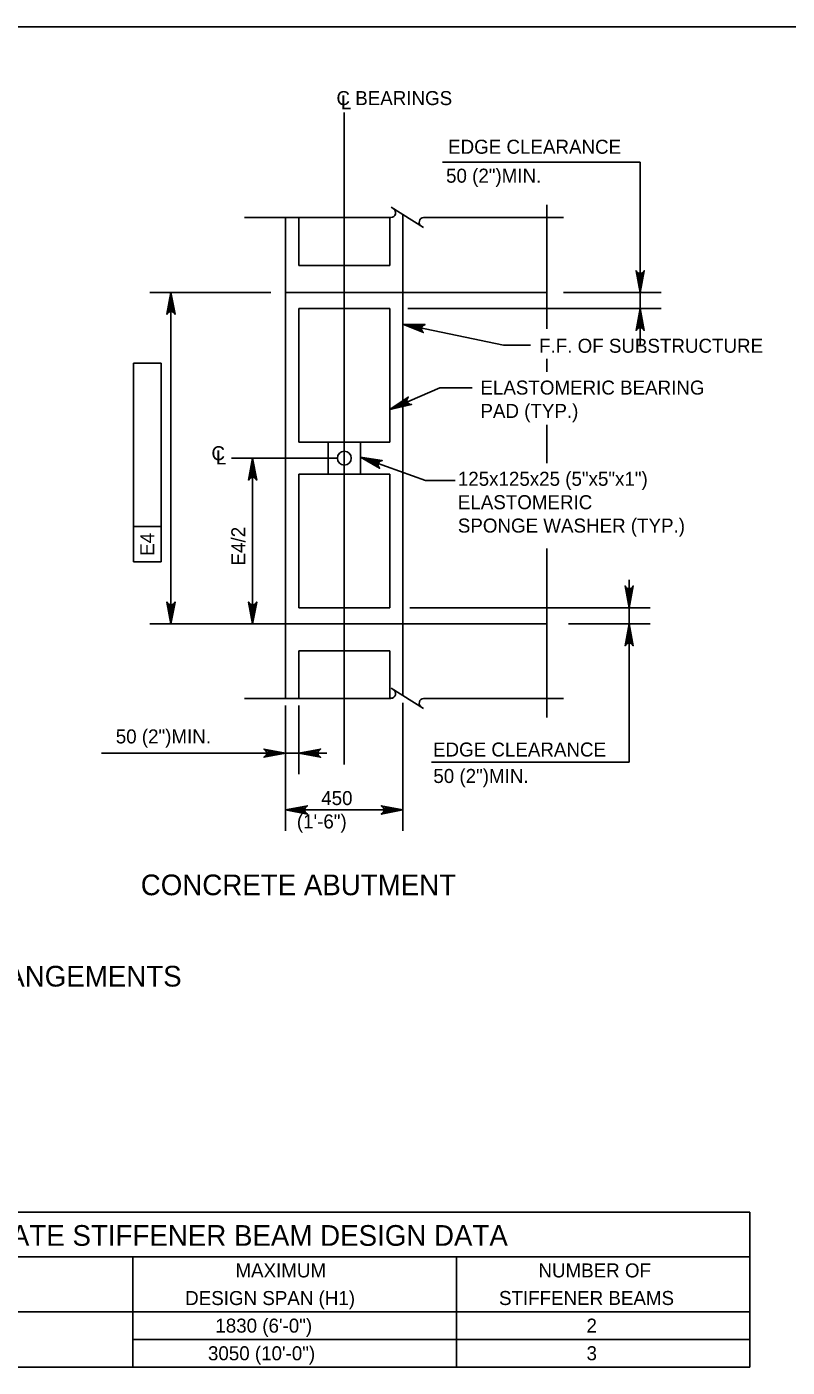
# Model space of a CAD drawing. Extents: x 638268 to 640277, y 295465 to 298435.
# Drawn here: x 639926.8 to 640089.4, y 297539.8 to 297826.5 of the extents above; entities that cross this region are included whole.
import ezdxf

# ---------------------------------------------------------------- set-up
doc = ezdxf.new("R2010")
doc.units = 0
for name, color, linetype in [('2', 7, 'Continuous'), ('3', 7, 'Continuous'), ('4', 7, 'Continuous'), ('8', 7, 'Continuous')]:
    doc.layers.add(name, color=color, linetype=linetype)

msp = doc.modelspace()

# ---------------------------------------------------------------- linework, layer by layer
at = {"layer": '2'}
msp.add_line((639316.46, 297826.46), (640102.46, 297826.46), dxfattribs=at)
at = {"layer": '3'}
for p, q in [((640004.71, 297787.87), (640011.64, 297783.51)), ((640038.02, 297788.37), (640038.02, 297761.88)), ((639973.35, 297785.69), (640004.63, 297785.69)), ((639982.12, 297682.85), (639982.12, 297785.69)), ((640007.22, 297786.29), (640007.22, 297683.45)), ((640011.63, 297785.69), (640041.52, 297785.69)), ((639984.93, 297775.38), (640004.41, 297775.38)), ((639978.92, 297769.64), (639953.09, 297769.64)), ((639957.59, 297698.77), (639957.59, 297769.64)), ((639982.12, 297769.64), (640038.02, 297769.64)), ((639984.93, 297766.19), (640004.41, 297766.19)), ((640038.02, 297755.46), (640038.02, 297752.64)), ((640038.02, 297741.36), (640038.02, 297733.14)), ((639984.93, 297737.65), (640004.41, 297737.65)), ((639984.93, 297730.76), (640004.41, 297730.76)), ((640038.02, 297714.9), (640038.02, 297678.78)), ((639984.93, 297702.22), (640004.41, 297702.22)), ((639979.62, 297698.77), (639953.09, 297698.77)), ((639982.12, 297698.77), (640038.02, 297698.77)), ((639984.93, 297693.03), (640004.41, 297693.03)), ((640004.71, 297685.03), (640011.64, 297680.68)), ((639973.35, 297682.85), (640004.63, 297682.85)), ((640011.63, 297682.85), (640041.52, 297682.85))]:
    msp.add_line(p, q, dxfattribs=at)
for points in [[(639957.09, 297766.64), (639958.09, 297766.64), (639957.59, 297769.64)], [(639957.09, 297701.77), (639958.09, 297701.77), (639957.59, 297698.77)]]:
    msp.add_lwpolyline(points, close=True, dxfattribs=at)
for centre, start, end in [((640004.63, 297786.71), 270, 60), ((640011.72, 297784.67), 95.3286, 237.8672), ((640004.63, 297683.88), 270, 60), ((640011.72, 297681.83), 95.3286, 237.8672)]:
    msp.add_arc(centre, 1.02, start, end, dxfattribs=at)
at = {"layer": '4'}
for p, q in [((639994.67, 297668.74), (639994.67, 297808.16)), ((640015.69, 297797.49), (640057.96, 297797.49)), ((640057.96, 297769.64), (640057.96, 297797.49)), ((640041.52, 297769.64), (640062.46, 297769.64)), ((640057.96, 297766.19), (640057.96, 297769.64)), ((640008.28, 297766.19), (640062.46, 297766.19)), ((640057.96, 297766.19), (640057.96, 297758.34)), ((640028.73, 297758.36), (640034.52, 297758.36)), ((639949.56, 297712.01), (639949.56, 297754.53)), ((639949.56, 297754.53), (639955.46, 297754.53)), ((639955.46, 297712.01), (639955.46, 297754.53)), ((640015.13, 297749.27), (640021.98, 297749.27)), ((639993.11, 297734.2), (639970.56, 297734.2)), ((639975.06, 297698.77), (639975.06, 297734.2)), ((640012.02, 297729.44), (640018.39, 297729.44)), ((639949.56, 297719.57), (639955.46, 297719.57)), ((639949.56, 297712.01), (639955.46, 297712.01)), ((640055.59, 297705.22), (640055.59, 297708.22)), ((640008.71, 297702.22), (640060.09, 297702.22)), ((640055.59, 297702.22), (640055.59, 297698.77)), ((639993.11, 297698.77), (639970.56, 297698.77)), ((640042.65, 297698.77), (640060.09, 297698.77)), ((640055.59, 297695.77), (640055.59, 297669.24)), ((640007.22, 297681.89), (640007.22, 297654.5)), ((639982.12, 297681.29), (639982.12, 297666.62)), ((639982.12, 297681.29), (639982.12, 297654.5)), ((639984.93, 297681.29), (639984.93, 297666.62)), ((639979.12, 297671.12), (639942.72, 297671.12)), ((639984.93, 297671.12), (639982.12, 297671.12)), ((639987.93, 297671.12), (639990.93, 297671.12)), ((640013.33, 297669.24), (640055.59, 297669.24)), ((640007.22, 297659), (639982.12, 297659))]:
    msp.add_line(p, q, dxfattribs=at)
for points in [[(640057.96, 297769.64), (640057.08, 297774.3), (640057.33, 297773.94), (640057.64, 297773.75), (640057.96, 297773.7), (640058.27, 297773.75), (640058.58, 297773.94), (640058.83, 297774.3), (640057.96, 297769.64), (640058.58, 297773.94), (640058.27, 297773.75), (640057.96, 297769.64), (640057.96, 297773.7), (640057.64, 297773.75), (640057.96, 297769.64), (640057.33, 297773.94)], [(639957.59, 297769.64), (639958.47, 297764.98), (639958.22, 297765.34), (639957.91, 297765.52), (639957.59, 297765.57), (639957.28, 297765.52), (639956.97, 297765.34), (639956.72, 297764.98), (639957.59, 297769.64), (639956.97, 297765.34), (639957.28, 297765.52), (639957.59, 297769.64), (639957.59, 297765.57), (639957.91, 297765.52), (639957.59, 297769.64), (639958.22, 297765.34)], [(640057.96, 297766.19), (640058.83, 297761.53), (640058.58, 297761.89), (640058.27, 297762.08), (640057.96, 297762.13), (640057.64, 297762.08), (640057.33, 297761.89), (640057.08, 297761.53), (640057.96, 297766.19), (640057.33, 297761.89), (640057.64, 297762.08), (640057.96, 297766.19), (640057.96, 297762.13), (640058.27, 297762.08), (640057.96, 297766.19), (640058.58, 297761.89)], [(640007.22, 297762.89), (640028.73, 297758.36)], [(640007.22, 297762.89), (640011.96, 297762.78), (640011.56, 297762.61), (640011.31, 297762.35), (640011.19, 297762.05), (640011.18, 297761.74), (640011.3, 297761.39), (640011.6, 297761.07), (640007.22, 297762.89), (640011.3, 297761.39), (640011.18, 297761.74), (640007.22, 297762.89), (640011.19, 297762.05), (640011.31, 297762.35), (640007.22, 297762.89), (640011.56, 297762.61)], [(640004.41, 297744.64), (640015.13, 297749.26)], [(640004.41, 297744.64), (640008.35, 297747.29), (640008.12, 297746.92), (640008.07, 297746.56), (640008.14, 297746.25), (640008.32, 297745.99), (640008.61, 297745.77), (640009.04, 297745.69), (640004.41, 297744.64), (640008.61, 297745.77), (640008.32, 297745.99), (640004.41, 297744.64), (640008.14, 297746.25), (640008.07, 297746.56), (640004.41, 297744.64), (640008.12, 297746.92)], [(639975.06, 297734.2), (639975.94, 297729.54), (639975.69, 297729.9), (639975.38, 297730.09), (639975.06, 297730.14), (639974.75, 297730.09), (639974.44, 297729.9), (639974.19, 297729.54), (639975.06, 297734.2), (639974.44, 297729.9), (639974.75, 297730.09), (639975.06, 297734.2), (639975.06, 297730.14), (639975.38, 297730.09), (639975.06, 297734.2), (639975.69, 297729.9)], [(639998.11, 297734.44), (640012.02, 297729.44)], [(639998.11, 297734.44), (640002.79, 297733.69), (640002.37, 297733.57), (640002.09, 297733.34), (640001.94, 297733.07), (640001.88, 297732.75), (640001.95, 297732.4), (640002.2, 297732.04), (639998.11, 297734.44), (640001.95, 297732.4), (640001.88, 297732.75), (639998.11, 297734.44), (640001.94, 297733.07), (640002.09, 297733.34), (639998.11, 297734.44), (640002.37, 297733.57)], [(640055.59, 297702.22), (640054.72, 297706.88), (640054.97, 297706.52), (640055.28, 297706.33), (640055.59, 297706.28), (640055.91, 297706.33), (640056.22, 297706.52), (640056.47, 297706.88), (640055.59, 297702.22), (640056.22, 297706.52), (640055.91, 297706.33), (640055.59, 297702.22), (640055.59, 297706.28), (640055.28, 297706.33), (640055.59, 297702.22), (640054.97, 297706.52)], [(639957.59, 297698.77), (639956.72, 297703.43), (639956.97, 297703.07), (639957.28, 297702.89), (639957.59, 297702.83), (639957.91, 297702.89), (639958.22, 297703.07), (639958.47, 297703.43), (639957.59, 297698.77), (639958.22, 297703.07), (639957.91, 297702.89), (639957.59, 297698.77), (639957.59, 297702.83), (639957.28, 297702.89), (639957.59, 297698.77), (639956.97, 297703.07)], [(639975.06, 297698.77), (639974.19, 297703.43), (639974.44, 297703.07), (639974.75, 297702.89), (639975.06, 297702.83), (639975.38, 297702.89), (639975.69, 297703.07), (639975.94, 297703.43), (639975.06, 297698.77), (639975.69, 297703.07), (639975.38, 297702.89), (639975.06, 297698.77), (639975.06, 297702.83), (639974.75, 297702.89), (639975.06, 297698.77), (639974.44, 297703.07)], [(640055.59, 297698.77), (640056.47, 297694.11), (640056.22, 297694.47), (640055.91, 297694.65), (640055.59, 297694.71), (640055.28, 297694.65), (640054.97, 297694.47), (640054.72, 297694.11), (640055.59, 297698.77), (640054.97, 297694.47), (640055.28, 297694.65), (640055.59, 297698.77), (640055.59, 297694.71), (640055.91, 297694.65), (640055.59, 297698.77), (640056.22, 297694.47)], [(639982.12, 297671.12), (639977.46, 297670.24), (639977.82, 297670.49), (639978, 297670.8), (639978.06, 297671.12), (639978, 297671.43), (639977.82, 297671.74), (639977.46, 297671.99), (639982.12, 297671.12), (639977.82, 297671.74), (639978, 297671.43), (639982.12, 297671.12), (639978.06, 297671.12), (639978, 297670.8), (639982.12, 297671.12), (639977.82, 297670.49)], [(639984.93, 297671.12), (639989.59, 297671.99), (639989.23, 297671.74), (639989.04, 297671.43), (639988.99, 297671.12), (639989.04, 297670.8), (639989.23, 297670.49), (639989.59, 297670.24), (639984.93, 297671.12), (639989.23, 297670.49), (639989.04, 297670.8), (639984.93, 297671.12), (639988.99, 297671.12), (639989.04, 297671.43), (639984.93, 297671.12), (639989.23, 297671.74)], [(639982.12, 297659), (639986.78, 297659.87), (639986.42, 297659.62), (639986.24, 297659.31), (639986.18, 297659), (639986.24, 297658.68), (639986.42, 297658.37), (639986.78, 297658.12), (639982.12, 297659), (639986.42, 297658.37), (639986.24, 297658.68), (639982.12, 297659), (639986.18, 297659), (639986.24, 297659.31), (639982.12, 297659), (639986.42, 297659.62)], [(640007.22, 297659), (640002.56, 297658.12), (640002.92, 297658.37), (640003.1, 297658.68), (640003.16, 297659), (640003.1, 297659.31), (640002.92, 297659.62), (640002.56, 297659.87), (640007.22, 297659), (640002.92, 297659.62), (640003.1, 297659.31), (640007.22, 297659), (640003.16, 297659), (640003.1, 297658.68), (640007.22, 297659), (640002.92, 297658.37)]]:
    msp.add_lwpolyline(points, dxfattribs=at)
for points in [[(640057.46, 297772.64), (640058.46, 297772.64), (640057.96, 297769.64)], [(640057.46, 297763.19), (640058.46, 297763.19), (640057.96, 297766.19)], [(640007.22, 297762.89), (640010.1, 297762.03), (640010.21, 297762.52)], [(639974.56, 297731.2), (639975.56, 297731.2), (639975.06, 297734.2)], [(640055.09, 297705.22), (640056.09, 297705.22), (640055.59, 297702.22)], [(640055.09, 297695.77), (640056.09, 297695.77), (640055.59, 297698.77)], [(639979.12, 297671.62), (639979.12, 297670.62), (639982.12, 297671.12)], [(639987.93, 297671.62), (639987.93, 297670.62), (639984.93, 297671.12)], [(639985.12, 297659.5), (639985.12, 297658.5), (639982.12, 297659)], [(640004.22, 297659.5), (640004.22, 297658.5), (640007.22, 297659)]]:
    msp.add_lwpolyline(points, close=True, dxfattribs=at)
at = {"layer": '8'}
for p, q in [((639984.93, 297775.38), (639984.93, 297785.69)), ((640004.41, 297775.38), (640004.41, 297785.69)), ((639984.93, 297737.65), (639984.93, 297766.19)), ((640004.41, 297737.65), (640004.41, 297766.19)), ((639991.22, 297730.76), (639991.22, 297737.65)), ((639998.11, 297730.76), (639998.11, 297737.65)), ((639984.93, 297702.22), (639984.93, 297730.76)), ((640004.41, 297702.22), (640004.41, 297730.76)), ((639984.93, 297682.85), (639984.93, 297693.03)), ((640004.41, 297682.85), (640004.41, 297693.03)), ((639859.24, 297572.99), (640081.44, 297572.99)), ((640081.44, 297572.99), (640081.44, 297539.82)), ((639859.24, 297563.45), (640081.44, 297563.45)), ((639949.44, 297563.45), (639949.44, 297539.82)), ((640018.67, 297563.45), (640018.67, 297539.82)), ((639859.24, 297551.64), (640081.44, 297551.64)), ((639949.44, 297545.73), (640081.44, 297545.73)), ((639859.24, 297539.82), (640081.44, 297539.82))]:
    msp.add_line(p, q, dxfattribs=at)
msp.add_circle((639994.67, 297734.2), 1.48, dxfattribs=at)

# ---------------------------------------------------------------- texts
at = {"layer": '3'}
for s, p in [('CONCRETE ABUTMENT', (639951.13, 297640.75)), ('ELASTOMERIC BEARING PAD ARRANGEMENTS', (639823.62, 297621.22))]:
    msp.add_text(s, height=4.4292, dxfattribs=at).set_placement(p)
at = {"layer": '4'}
for s, height, p in [('C BEARINGS', 3, (639992.99, 297809.71)), ('L', 3, (639993.94, 297808.8)), ('EDGE CLEARANCE', 3, (640016.87, 297799.31)), ('50 (2")MIN.', 3, (640016.43, 297793.12)), ('F.F. OF SUBSTRUCTURE', 3, (640036.33, 297756.75)), ('ELASTOMERIC BEARING', 3, (640023.78, 297747.81)), ('PAD (TYP.)', 3, (640023.78, 297742.81)), ('C', 3, (639966.25, 297733.77)), ('L', 3, (639967.2, 297732.86)), ('125x125x25 (5"x5"x1")', 3, (640018.95, 297728.3)), ('ELASTOMERIC', 3, (640018.95, 297723.3)), ('SPONGE WASHER (TYP.)', 3, (640018.95, 297718.3)), ('50 (2")MIN.', 3, (639945.78, 297673.21)), ('EDGE CLEARANCE', 3, (640013.64, 297670.41)), ('50 (2")MIN.', 3, (640013.71, 297664.75)), ('450', 3, (639989.73, 297660.03)), ('(1\'-6")', 3, (639984.52, 297655.03)), ('TABLE 1 - INTERMEDIATE STIFFENER BEAM DESIGN DATA', 4.4292, (639861.81, 297565.78)), ('MAXIMUM', 3, (639971.38, 297559.02)), ('NUMBER OF ', 3, (640036.19, 297559.02)), ('DESIGN SPAN (H1)', 3, (639960.63, 297553.11)), ('STIFFENER BEAMS', 3, (640027.75, 297553.12)), ('1830 (6\'-0")', 3, (639967.08, 297547.21)), ('2', 3, (640046.47, 297547.21)), ('3050 (10\'-0")', 3, (639965.5, 297541.3)), ('3', 3, (640046.48, 297541.31))]:
    msp.add_text(s, height=height, dxfattribs=at).set_placement(p)
for s, rotation, p in [('E4/2', 90, (639973.5, 297711.27)), ('E4', 89.9359, (639954.01, 297713.33))]:
    msp.add_text(s, height=3, rotation=rotation, dxfattribs=at).set_placement(p)

doc.saveas('drawing.dxf')
